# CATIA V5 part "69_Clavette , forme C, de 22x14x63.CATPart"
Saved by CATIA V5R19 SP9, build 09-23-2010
Part number: 69_Clavette , forme C, de 22x14x63
Revision: ANY
Definition: UNKNOWN
Nomenclature: 69_Clavette , forme C, de 22x14x63
Source: Unknown
Bounding box of the stored display mesh (mm): x -55 to 55, y -11 to 11, z -7 to 7
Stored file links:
  Y:\fin de projet cabestan poupee\69_Clavette , forme C, de 22x14x63.CATPart
  Ass_arbre poupee_1.CATProduct
  Y:\bricolage cabestan\6_axe.CATPart
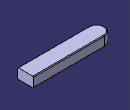
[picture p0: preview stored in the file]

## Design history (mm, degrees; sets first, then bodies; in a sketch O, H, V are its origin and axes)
Body1 "NONE" (main body)
  Solid1: solid without history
